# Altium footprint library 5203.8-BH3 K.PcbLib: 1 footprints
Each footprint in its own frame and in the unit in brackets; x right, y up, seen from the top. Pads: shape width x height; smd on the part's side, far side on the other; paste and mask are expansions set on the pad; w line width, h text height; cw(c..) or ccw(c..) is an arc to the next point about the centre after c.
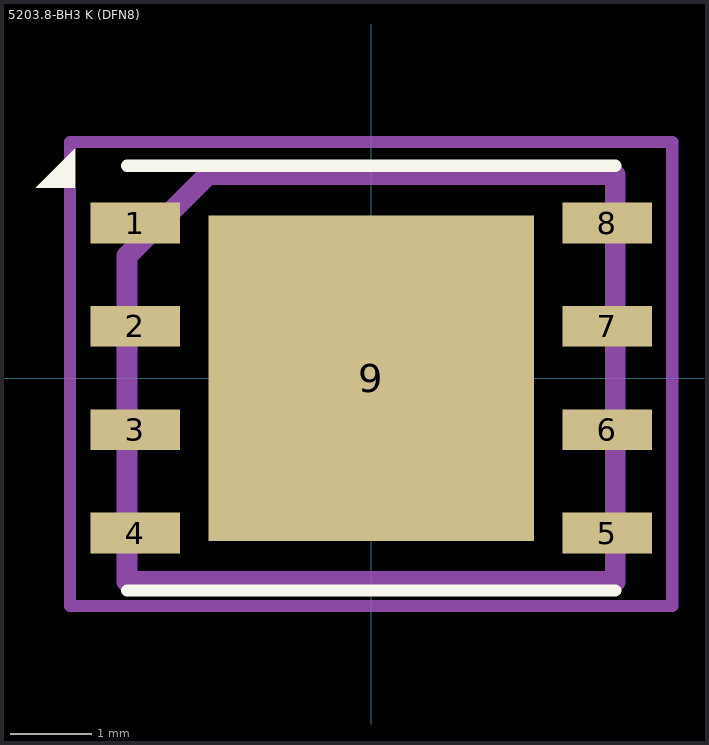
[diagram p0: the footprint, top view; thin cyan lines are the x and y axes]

## 5203.8-BH3 K (DFN8) [mm]
pads (9):
  rect 1.1x0.5 smd: 1(-2.9,1.905) 2(-2.9,0.635) 3(-2.9,-0.635) 4(-2.9,-1.905) 5(2.9,-1.905) 6(2.9,-0.635) 7(2.9,0.635) 8(2.9,1.905)
  rect 4x4 smd: 9(0,0)
F.SilkS:
  region: -3.64,2.34 -4.12,2.34 -3.64,2.82
  lines w0.15: -3,-2.61 3,-2.61 ; -3,2.61 3,2.61
F.CrtYd:
  lines w0.15: -3.7,-2.8 -3.7,2.9 3.7,2.9 3.7,-2.8 -3.7,-2.8
F.Fab:
  lines w0.254: -3,-2.5 -3,1.5 -2,2.5 3,2.5 3,-2.5 -3,-2.5
3D body "DFN8-5X6.step": height 0.95, standoff 0, extent -3.052,-2.5 3.048,2.5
